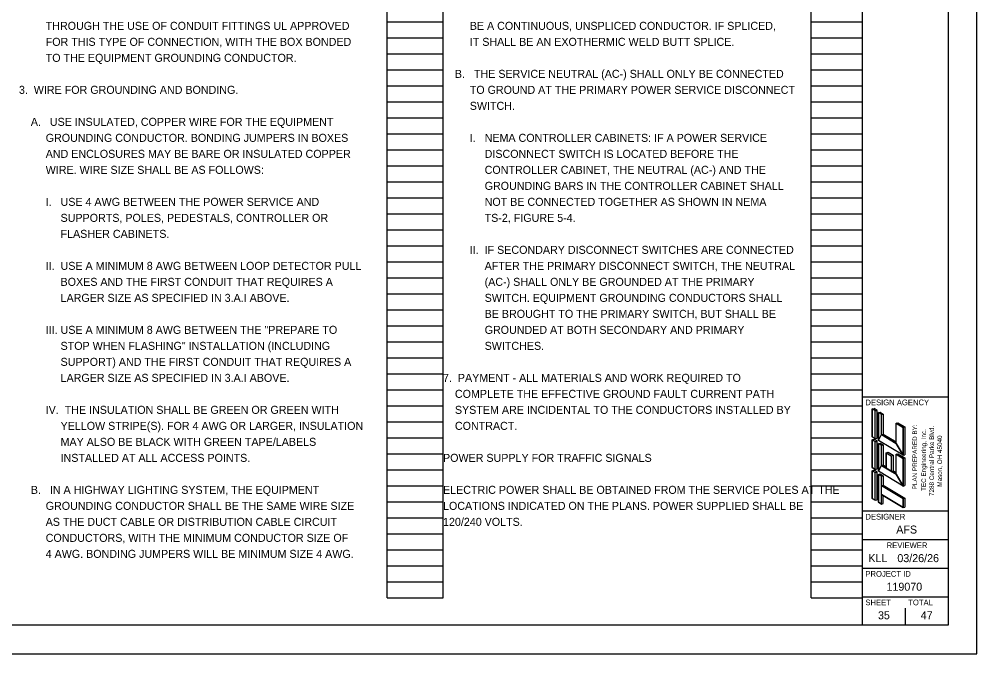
# Model space of a CAD drawing. Extents: x 0 to 34, y 0 to 22.
# Drawn here: x 17.24 to 34, y 0 to 11.11 of the extents above; entities that cross this region are included whole.
import ezdxf

# ---------------------------------------------------------------- set-up
doc = ezdxf.new("R2010")
doc.units = 0
for name, color, linetype in [('Default', 7, 'Continuous'), ('SH_Border', 7, 'Continuous'), ('SH_Cut_Line', 7, 'Continuous'), ('SH_Data', 7, 'Continuous'), ('SH_Text', 7, 'Continuous')]:
    doc.layers.add(name, color=color, linetype=linetype)

msp = doc.modelspace()

# ---------------------------------------------------------------- linework, layer by layer
at = {"layer": 'SH_Border'}
for p, q in [((32, 0.5), (32, 21.5)), ((32, 4.5), (33.5, 4.5)), ((32, 2.5), (33.5, 2.5)), ((32, 2), (33.5, 2)), ((32, 1.5), (33.5, 1.5)), ((32, 1), (33.5, 1))]:
    msp.add_line(p, q, dxfattribs=at)
msp.add_lwpolyline([(1.5, 21.5), (33.5, 21.5), (33.5, 0.5), (1.5, 0.5)], close=True, dxfattribs=at)
at = {"layer": 'SH_Cut_Line'}
msp.add_lwpolyline([(0, 0), (34, 0), (34, 22), (0, 22)], close=True, dxfattribs=at)
at = {"layer": 'SH_Data'}
for p, q in [((23.68, 0.98), (23.68, 21.14)), ((24.66, 0.98), (24.66, 21.14)), ((31.1, 0.98), (31.1, 21.14)), ((32, 0.98), (32, 21.14)), ((23.68, 11.06), (24.66, 11.06)), ((31.1, 11.06), (32, 11.06)), ((23.68, 10.78), (24.66, 10.78)), ((31.1, 10.78), (32, 10.78)), ((23.68, 10.5), (24.66, 10.5)), ((31.1, 10.5), (32, 10.5)), ((23.68, 10.22), (24.66, 10.22)), ((31.1, 10.22), (32, 10.22)), ((23.68, 9.94), (24.66, 9.94)), ((31.1, 9.94), (32, 9.94)), ((23.68, 9.66), (24.66, 9.66)), ((31.1, 9.66), (32, 9.66)), ((23.68, 9.38), (24.66, 9.38)), ((31.1, 9.38), (32, 9.38)), ((23.68, 9.1), (24.66, 9.1)), ((31.1, 9.1), (32, 9.1)), ((23.68, 8.82), (24.66, 8.82)), ((31.1, 8.82), (32, 8.82)), ((23.68, 8.54), (24.66, 8.54)), ((31.1, 8.54), (32, 8.54)), ((23.68, 8.26), (24.66, 8.26)), ((31.1, 8.26), (32, 8.26)), ((23.68, 7.98), (24.66, 7.98)), ((31.1, 7.98), (32, 7.98)), ((23.68, 7.7), (24.66, 7.7)), ((31.1, 7.7), (32, 7.7)), ((23.68, 7.42), (24.66, 7.42)), ((31.1, 7.42), (32, 7.42)), ((23.68, 7.14), (24.66, 7.14)), ((31.1, 7.14), (32, 7.14)), ((23.68, 6.86), (24.66, 6.86)), ((31.1, 6.86), (32, 6.86)), ((23.68, 6.58), (24.66, 6.58)), ((31.1, 6.58), (32, 6.58)), ((23.68, 6.3), (24.66, 6.3)), ((31.1, 6.3), (32, 6.3)), ((23.68, 6.02), (24.66, 6.02)), ((31.1, 6.02), (32, 6.02)), ((23.68, 5.74), (24.66, 5.74)), ((31.1, 5.74), (32, 5.74)), ((23.68, 5.46), (24.66, 5.46)), ((31.1, 5.46), (32, 5.46)), ((23.68, 5.18), (24.66, 5.18)), ((31.1, 5.18), (32, 5.18)), ((23.68, 4.9), (24.66, 4.9)), ((31.1, 4.9), (32, 4.9)), ((23.68, 4.62), (24.66, 4.62)), ((31.1, 4.62), (32, 4.62)), ((23.68, 4.34), (24.66, 4.34)), ((31.1, 4.34), (32, 4.34)), ((23.68, 4.06), (24.66, 4.06)), ((31.1, 4.06), (32, 4.06)), ((23.68, 3.78), (24.66, 3.78)), ((31.1, 3.78), (32, 3.78)), ((23.68, 3.5), (24.66, 3.5)), ((31.1, 3.5), (32, 3.5)), ((32.75, 3.5), (32.75, 3.5)), ((23.68, 3.22), (24.66, 3.22)), ((31.1, 3.22), (32, 3.22)), ((23.68, 2.94), (24.66, 2.94)), ((31.1, 2.94), (32, 2.94)), ((23.68, 2.66), (24.66, 2.66)), ((31.1, 2.66), (32, 2.66)), ((23.68, 2.38), (24.66, 2.38)), ((31.1, 2.38), (32, 2.38)), ((23.68, 2.1), (24.66, 2.1)), ((31.1, 2.1), (32, 2.1)), ((23.68, 1.82), (24.66, 1.82)), ((31.1, 1.82), (32, 1.82)), ((23.68, 1.54), (24.66, 1.54)), ((31.1, 1.54), (32, 1.54)), ((23.68, 1.26), (24.66, 1.26)), ((31.1, 1.26), (32, 1.26)), ((23.68, 0.98), (24.66, 0.98)), ((31.1, 0.98), (32, 0.98)), ((32.375, 0.675), (32.375, 0.675)), ((32.75, 0.5), (32.75, 0.8))]:
    msp.add_line(p, q, dxfattribs=at)
at = {"layer": 'SH_Text'}
for p, q in [((32.169, 4.285), (32.201, 4.294)), ((32.169, 3.799), (32.169, 4.285)), ((32.223, 4.253), (32.169, 4.285)), ((32.255, 4.261), (32.201, 4.294)), ((32.223, 4.253), (32.255, 4.261)), ((32.223, 3.767), (32.223, 4.253)), ((32.255, 3.775), (32.255, 4.261)), ((32.277, 4.221), (32.309, 4.229)), ((32.331, 4.188), (32.277, 4.221)), ((32.277, 3.735), (32.277, 4.221)), ((32.309, 4.229), (32.363, 4.196)), ((32.331, 4.188), (32.363, 4.196)), ((32.363, 4.196), (32.363, 3.845)), ((32.331, 3.837), (32.331, 4.188)), ((32.587, 4.034), (32.62, 4.042)), ((32.587, 3.683), (32.587, 4.034)), ((32.709, 3.961), (32.587, 4.034)), ((32.62, 4.042), (32.741, 3.97)), ((32.709, 3.961), (32.741, 3.97)), ((32.709, 3.475), (32.709, 3.961)), ((32.741, 3.97), (32.741, 3.484)), ((32.223, 3.767), (32.169, 3.799)), ((32.169, 3.745), (32.201, 3.754)), ((32.169, 3.259), (32.169, 3.745)), ((32.223, 3.713), (32.169, 3.745)), ((32.255, 3.722), (32.201, 3.754)), ((32.223, 3.767), (32.255, 3.775)), ((32.223, 3.713), (32.255, 3.722)), ((32.223, 3.227), (32.223, 3.713)), ((32.255, 3.236), (32.255, 3.722)), ((32.709, 3.475), (32.277, 3.735)), ((32.277, 3.681), (32.309, 3.689)), ((32.309, 3.689), (32.363, 3.656)), ((32.331, 3.837), (32.363, 3.845)), ((32.587, 3.683), (32.331, 3.837)), ((32.363, 3.845), (32.587, 3.711)), ((32.277, 3.195), (32.277, 3.681)), ((32.331, 3.648), (32.277, 3.681)), ((32.331, 3.648), (32.363, 3.656)), ((32.331, 3.297), (32.331, 3.648)), ((32.363, 3.656), (32.363, 3.305)), ((32.415, 3.519), (32.448, 3.527)), ((32.415, 3.519), (32.415, 3.247)), ((32.415, 3.519), (32.503, 3.466)), ((32.448, 3.527), (32.535, 3.474)), ((32.503, 3.466), (32.535, 3.474)), ((32.503, 3.466), (32.503, 3.194)), ((32.535, 3.474), (32.535, 3.202)), ((32.587, 3.494), (32.62, 3.502)), ((32.587, 3.143), (32.587, 3.494)), ((32.709, 3.421), (32.587, 3.494)), ((32.62, 3.502), (32.741, 3.43)), ((32.709, 3.475), (32.741, 3.484)), ((32.709, 3.421), (32.741, 3.43)), ((32.709, 2.935), (32.709, 3.421)), ((32.741, 3.43), (32.741, 2.944)), ((32.223, 3.227), (32.169, 3.259)), ((32.169, 3.205), (32.201, 3.215)), ((32.169, 2.719), (32.169, 3.205)), ((32.223, 3.173), (32.169, 3.205)), ((32.255, 3.181), (32.201, 3.215)), ((32.223, 3.227), (32.255, 3.236)), ((32.709, 2.935), (32.277, 3.195)), ((32.331, 3.297), (32.363, 3.305)), ((32.415, 3.247), (32.331, 3.297)), ((32.363, 3.305), (32.415, 3.274)), ((32.503, 3.194), (32.535, 3.202)), ((32.587, 3.143), (32.503, 3.194)), ((32.535, 3.202), (32.587, 3.171)), ((32.222, 3.173), (32.255, 3.181)), ((32.223, 2.687), (32.223, 3.173)), ((32.255, 2.695), (32.255, 3.181)), ((32.277, 3.141), (32.309, 3.151)), ((32.331, 3.108), (32.277, 3.141)), ((32.277, 2.655), (32.277, 3.141)), ((32.309, 3.151), (32.363, 3.116)), ((32.331, 3.108), (32.363, 3.116)), ((32.331, 2.944), (32.331, 3.108)), ((32.363, 3.116), (32.363, 2.952)), ((32.331, 2.944), (32.363, 2.952)), ((32.331, 2.944), (32.709, 2.717)), ((32.363, 2.952), (32.741, 2.725)), ((32.709, 2.935), (32.741, 2.944)), ((32.223, 2.687), (32.169, 2.719)), ((32.223, 2.687), (32.255, 2.695)), ((32.331, 2.787), (32.709, 2.56)), ((32.331, 2.622), (32.331, 2.787)), ((32.363, 2.63), (32.363, 2.767)), ((32.709, 2.717), (32.741, 2.725)), ((32.709, 2.56), (32.709, 2.717)), ((32.741, 2.725), (32.741, 2.568)), ((32.331, 2.622), (32.277, 2.655)), ((32.331, 2.622), (32.363, 2.63)), ((32.709, 2.56), (32.741, 2.568))]:
    msp.add_line(p, q, dxfattribs=at)
for points in [[(32.169, 3.799), (32.223, 3.767), (32.223, 4.253), (32.169, 4.285)], [(32.277, 3.735), (32.331, 3.837), (32.331, 4.188), (32.277, 4.221)], [(32.709, 3.475), (32.587, 3.683), (32.587, 4.034), (32.709, 3.961)], [(32.169, 3.259), (32.223, 3.227), (32.223, 3.713), (32.169, 3.745)], [(32.277, 3.735), (32.331, 3.837), (32.587, 3.683), (32.709, 3.475)], [(32.277, 3.195), (32.331, 3.297), (32.331, 3.648), (32.277, 3.681)], [(32.415, 3.247), (32.415, 3.519), (32.503, 3.466), (32.503, 3.194)], [(32.709, 2.935), (32.587, 3.143), (32.587, 3.494), (32.709, 3.421)], [(32.169, 2.719), (32.223, 2.687), (32.223, 3.173), (32.169, 3.205)], [(32.277, 3.195), (32.331, 3.297), (32.587, 3.143), (32.709, 2.935)], [(32.277, 2.655), (32.331, 2.622), (32.331, 3.108), (32.277, 3.141)], [(32.331, 2.787), (32.331, 2.944), (32.709, 2.717), (32.709, 2.56)]]:
    msp.add_lwpolyline(points, close=True, dxfattribs=at)

# ---------------------------------------------------------------- texts
at = {"layer": 'Default'}
for s, p in [('PLAN PREPARED BY:', (32.954, 2.88)), ('TEC Engineering, Inc.', (33.11, 2.851)), ('7288 Central Parke Blvd.', (33.25, 2.762)), ('Mason, OH 45040', (33.39, 2.925))]:
    msp.add_text(s, height=0.08, rotation=90, dxfattribs=at).set_placement(p)
at = {"layer": 'SH_Data'}
for s, height, p in [('DESIGN AGENCY', 0.1, (32.05, 4.35)), ('DESIGNER', 0.1, (32.05, 2.35)), ('AFS', 0.14, (32.59, 2.105)), ('REVIEWER', 0.1, (32.422, 1.85)), ('KLL', 0.14, (32.101, 1.605)), ('03/26/26', 0.14, (32.609, 1.605)), ('PROJECT ID', 0.1, (32.05, 1.35)), ('119070', 0.14, (32.419, 1.105)), ('SHEET', 0.1, (32.05, 0.85)), ('TOTAL', 0.1, (32.8, 0.85)), ('35', 0.14, (32.27, 0.605)), ('47', 0.14, (33.018, 0.605))]:
    msp.add_text(s, height=height, dxfattribs=at).set_placement(p)
at = {"layer": 'SH_Text'}
for s, p in [('         THROUGH THE USE OF CONDUIT FITTINGS UL APPROVED', (17.24, 10.92)), ('         BE A CONTINUOUS, UNSPLICED CONDUCTOR. IF SPLICED,', (24.66, 10.92)), ('         FOR THIS TYPE OF CONNECTION, WITH THE BOX BONDED', (17.24, 10.64)), ('         IT SHALL BE AN EXOTHERMIC WELD BUTT SPLICE.', (24.66, 10.64)), ('         TO THE EQUIPMENT GROUNDING CONDUCTOR.', (17.24, 10.36)), ('    B.   THE SERVICE NEUTRAL (AC-) SHALL ONLY BE CONNECTED', (24.66, 10.08)), ('3.  WIRE FOR GROUNDING AND BONDING.', (17.24, 9.8)), ('         TO GROUND AT THE PRIMARY POWER SERVICE DISCONNECT', (24.66, 9.8)), ('         SWITCH.', (24.66, 9.52)), ('    A.   USE INSULATED, COPPER WIRE FOR THE EQUIPMENT', (17.24, 9.24)), ('         GROUNDING CONDUCTOR. BONDING JUMPERS IN BOXES', (17.24, 8.96)), ('         I.   NEMA CONTROLLER CABINETS: IF A POWER SERVICE', (24.66, 8.96)), ('         AND ENCLOSURES MAY BE BARE OR INSULATED COPPER', (17.24, 8.68)), ('              DISCONNECT SWITCH IS LOCATED BEFORE THE', (24.66, 8.68)), ('              CONTROLLER CABINET, THE NEUTRAL (AC-) AND THE', (24.66, 8.4)), ('         WIRE. WIRE SIZE SHALL BE AS FOLLOWS:', (17.24, 8.4)), ('              GROUNDING BARS IN THE CONTROLLER CABINET SHALL', (24.66, 8.12)), ('         I.   USE 4 AWG BETWEEN THE POWER SERVICE AND', (17.24, 7.84)), ('              NOT BE CONNECTED TOGETHER AS SHOWN IN NEMA', (24.66, 7.84)), ('              SUPPORTS, POLES, PEDESTALS, CONTROLLER OR', (17.24, 7.56)), ('              TS-2, FIGURE 5-4.', (24.66, 7.56)), ('              FLASHER CABINETS.', (17.24, 7.28)), ('         II.  IF SECONDARY DISCONNECT SWITCHES ARE CONNECTED', (24.66, 7)), ('         II.  USE A MINIMUM 8 AWG BETWEEN LOOP DETECTOR PULL', (17.24, 6.72)), ('              AFTER THE PRIMARY DISCONNECT SWITCH, THE NEUTRAL', (24.66, 6.72)), ('              BOXES AND THE FIRST CONDUIT THAT REQUIRES A', (17.24, 6.44)), ('              (AC-) SHALL ONLY BE GROUNDED AT THE PRIMARY', (24.66, 6.44)), ('              LARGER SIZE AS SPECIFIED IN 3.A.I ABOVE.', (17.24, 6.16)), ('              SWITCH. EQUIPMENT GROUNDING CONDUCTORS SHALL', (24.66, 6.16)), ('              BE BROUGHT TO THE PRIMARY SWITCH, BUT SHALL BE', (24.66, 5.88)), ('         III. USE A MINIMUM 8 AWG BETWEEN THE "PREPARE TO', (17.24, 5.6)), ('              GROUNDED AT BOTH SECONDARY AND PRIMARY', (24.66, 5.6)), ('              STOP WHEN FLASHING" INSTALLATION (INCLUDING', (17.24, 5.32)), ('              SWITCHES.', (24.66, 5.32)), ('              SUPPORT) AND THE FIRST CONDUIT THAT REQUIRES A', (17.24, 5.04)), ('              LARGER SIZE AS SPECIFIED IN 3.A.I ABOVE.', (17.24, 4.76)), ('7.  PAYMENT - ALL MATERIALS AND WORK REQUIRED TO', (24.66, 4.76)), ('    COMPLETE THE EFFECTIVE GROUND FAULT CURRENT PATH', (24.66, 4.48)), ('         IV.  THE INSULATION SHALL BE GREEN OR GREEN WITH', (17.24, 4.2)), ('    SYSTEM ARE INCIDENTAL TO THE CONDUCTORS INSTALLED BY', (24.66, 4.2)), ('              YELLOW STRIPE(S). FOR 4 AWG OR LARGER, INSULATION', (17.24, 3.92)), ('    CONTRACT.', (24.66, 3.92)), ('              MAY ALSO BE BLACK WITH GREEN TAPE/LABELS', (17.24, 3.64)), ('              INSTALLED AT ALL ACCESS POINTS.', (17.24, 3.36)), ('POWER SUPPLY FOR TRAFFIC SIGNALS', (24.66, 3.36)), ('    B.   IN A HIGHWAY LIGHTING SYSTEM, THE EQUIPMENT', (17.24, 2.8)), ('ELECTRIC POWER SHALL BE OBTAINED FROM THE SERVICE POLES AT THE ', (24.66, 2.8)), ('         GROUNDING CONDUCTOR SHALL BE THE SAME WIRE SIZE', (17.24, 2.52)), ('LOCATIONS INDICATED ON THE PLANS. POWER SUPPLIED SHALL BE ', (24.66, 2.52)), ('         AS THE DUCT CABLE OR DISTRIBUTION CABLE CIRCUIT', (17.24, 2.24)), ('120/240 VOLTS.', (24.66, 2.24)), ('         CONDUCTORS, WITH THE MINIMUM CONDUCTOR SIZE OF', (17.24, 1.96)), ('         4 AWG. BONDING JUMPERS WILL BE MINIMUM SIZE 4 AWG.', (17.24, 1.68))]:
    msp.add_text(s, height=0.14, dxfattribs=at).set_placement(p)

doc.saveas('drawing.dxf')
